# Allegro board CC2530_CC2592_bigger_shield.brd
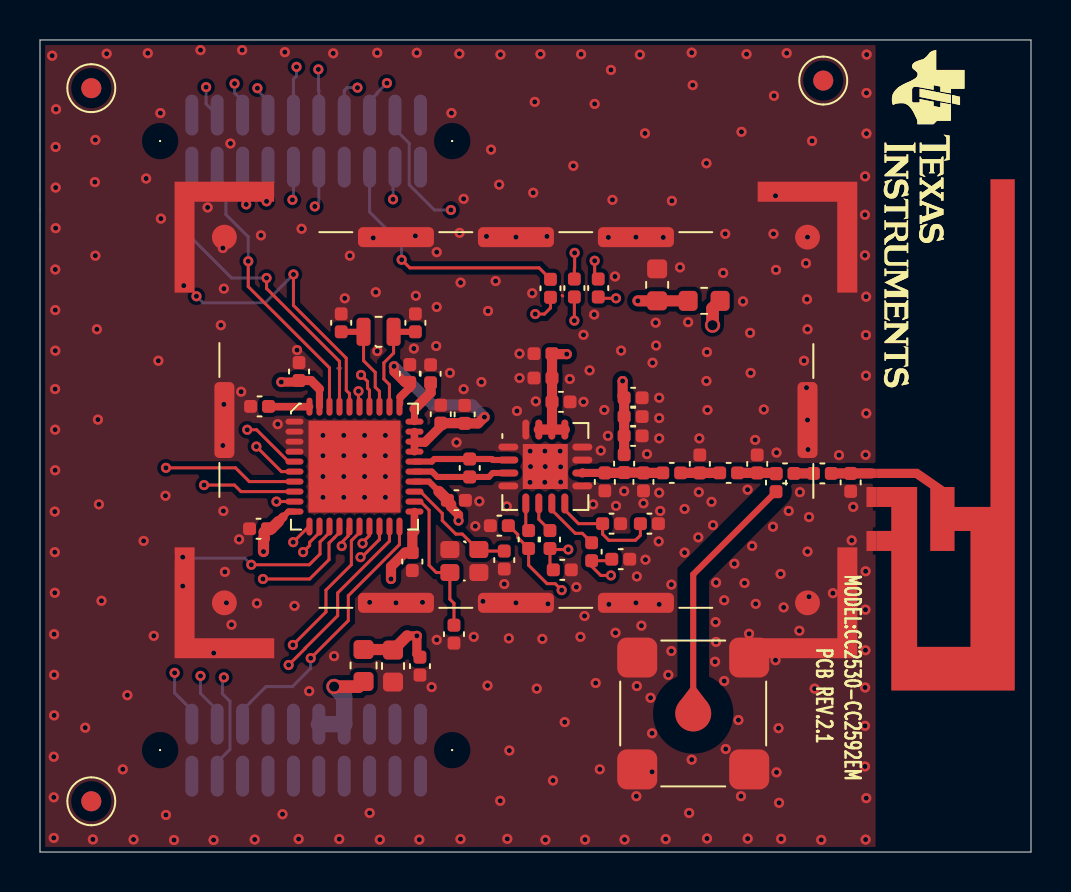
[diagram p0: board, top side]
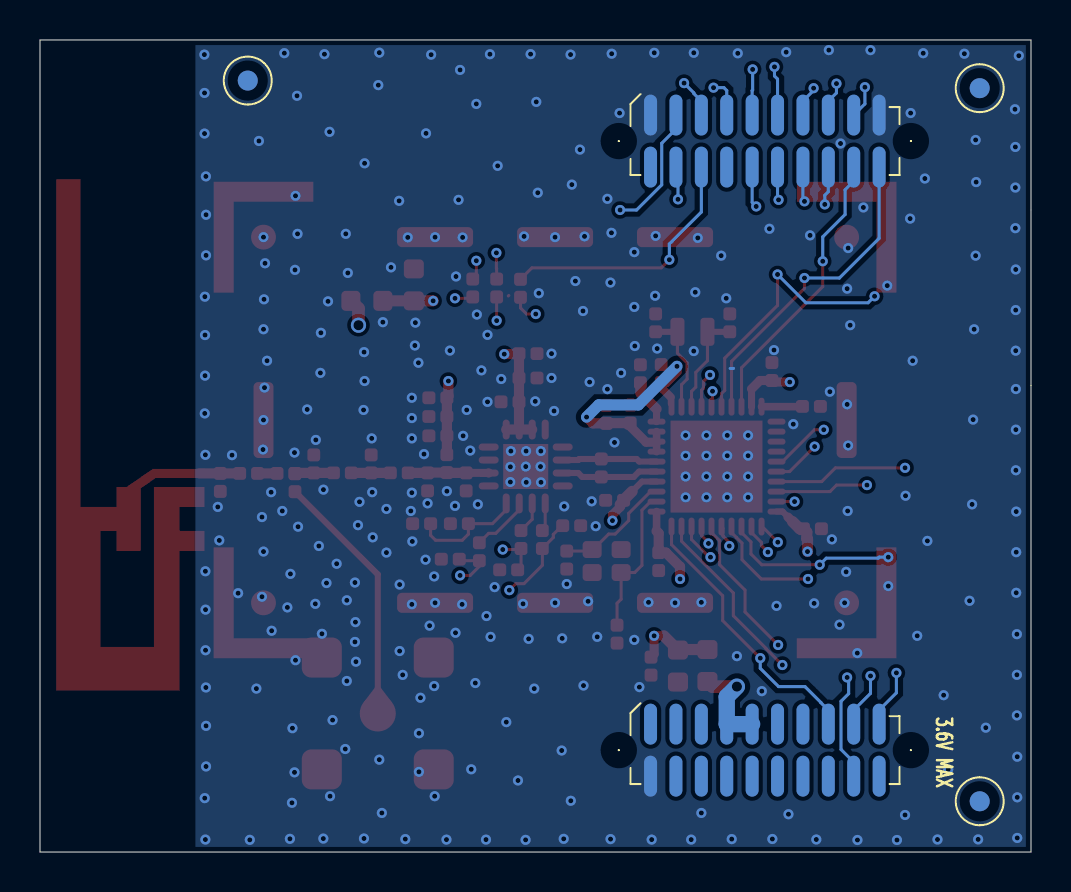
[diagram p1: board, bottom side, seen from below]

Outline 49.56 x 40.64 mm; copper layers: TOP, GND, SIGNAL_A, BOTTOM. Coordinates in mm from the lower left corner of the outline.
Outline path: 0,40.64 0,0 49.56,0 49.56,40.64 0,40.64

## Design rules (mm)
nets with their own width: min track width 0.305; nets RF_N RF_P
nets with their own width: min track width 0.457; nets VDD_CC2530
nets with their own width: min track width 0.508; nets VDD_CC2592
nets with their own width: min track width 0.635; nets VDD_EB

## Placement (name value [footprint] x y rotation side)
A2  2.4GHz  [ANTENNA_DN007AN]  41.58 18.95 270 top
C2  2.2uF  [CAPC1608X90N]  17.65 10.11 270 top
C4  DNM  [CAPC1005X60N]  19 9.75 270 top
C5  2.2uF  [CAPC1608X90N]  30.86 27.58 90 top
C101  100nF  [CAPC1005X60N]  11.38 16.18 180 top
C211  100nF  [CAPC1005X60N]  18.62 14.99 270 top
C221  12pF  [CAPC1005X60N]  20.7 11.35 270 top
C231  12pF  [CAPC1005X60N]  23.22 15.06 270 top
C241  100nF  [CAPC1005X60N]  20.37 17.6 0 top
C271  100nF  [CAPC1005X60N]  21.23 22.35 270 top
C272  220pF  [CAPC1005X60N]  20.04 21.46 90 top
C311  100nF  [CAPC1005X60N]  18.49 23.5 90 top
C321  22pF  [CAPC1005X60N]  18.77 26.04 90 top
C331  22pF  [CAPC1005X60N]  15.06 26.04 90 top
C391  1uF  [CAPC1005X60N]  12.95 23.6 90 top
C401  1uF  [CAPC1005X60N]  11.43 22.3 180 top
C3051  DNM  [CAPC1005X60N]  23.42 16.33 180 top
C3061  DNM  [CAPC1005X60N]  26.57 14.12 180 top
C3071  DNM  [CAPC1005X60N]  29.49 14.66 180 top
C3081  DNM  [CAPC1005X60N]  30.02 16.43 0 top
C3101  2.2pF  [CAPC1005X60N]  28.24 18.97 270 top
C3102  DNM  [CAPC1005X60N]  30.18 18.97 270 top
C3103  2.2pF  [CAPC1005X60N]  32.99 18.97 90 top
C3105  0.3pF  [CAPC1005X60N]  35.86 18.97 90 top
C3106  12pF  [CAPC1005X60N]  29.21 20.83 0 top
C3107  1nF  [CAPC1005X60N]  29.21 21.79 0 top
C3108  1uF  [CAPC1005X60N]  29.21 22.73 0 top
C3109  DNM  [CAPC1005X60N]  40.54 18.95 270 top
C3110  18pF  [CAPC1005X60N]  36.8 18.03 90 top
C3111  DNM  [CAPC1005X60N]  36.8 18.95 0 top
C3131  12pF  [CAPC1005X60N]  25.6 22.53 0 top
C3132  1nF  [CAPC1005X60N]  25.6 23.72 180 top
C3133  DNM  [CAPC1005X60N]  25.6 24.94 180 top
FIDU1  FIDU_1MM  [FID100X115]  2.57 2.54 180 bottom
FIDU2  FIDU_1MM  [FID100X115]  39.17 38.61 180 bottom
FIDU3  FIDU_1MM  [FID100X115]  2.57 38.23 180 bottom
FIDU4  FIDU_1MM  [FID100X115]  39.17 38.61 0 top
FIDU5  FIDU_1MM  [FID100X115]  2.57 2.54 0 top
FIDU6  FIDU_1MM  [FID100X115]  2.57 38.23 0 top
FL1  BLM18HE152SN1  [FIL_BLM18HE152SN1DN]  16.18 10.13 270 top
FL2  BLM18HE152SN1  [FIL_BLM18HE152SN1DN]  32.41 27.58 0 top
J3  SMA-10V21-TGG  [HUSTSAN_SMA10V21TGGAN]  32.66 6.93 0 top
L2526  3.9nH  [INDC1005X60N]  21.49 18.77 90 top
L3101  4.7nH  [INDC1005X60N]  29.21 19.89 270 top
L3102  1nH  [INDC1005X60N]  31.14 18.97 0 top
L3104  2nH  [INDC1005X60N]  33.99 18.97 0 top
P1  SFM-110-02-S-D-A-K-TR  [SAMTEC_SFM11002AN]  19.02 36.88 270 bottom
P2  SFM-110-02-S-D-A-K-TR  [SAMTEC_SFM11002AN]  19.02 6.4 270 bottom
R301  56k  [RESC1005X40N]  19.53 24.38 270 top
R3051  10k  [RESC1005X40N]  24.43 15.19 90 top
R3061  10k  [RESC1005X40N]  25.5 15.19 90 top
R3071  10k  [RESC1005X40N]  27.58 14.58 90 top
R3081  3.9k  [RESC1005X40N]  29.03 16.43 180 top
RP07  DNM  [RESC1005X40N]  26.72 28.68 270 top
RP10  DNM  [RESC1005X40N]  25.53 27.76 90 top
RP11  DNM  [RESC1005X40N]  27.91 28.68 270 top
RP12  0  [RESC1005X40N]  39.57 18.95 180 top
SC1  BMI-S-209-F  [MECH_BMIS209FN]  9.22 12.47 0 top
U5  CC2592  [QFNFC65P400X400X100-17AN]  23.42 20.27 270 top
U7  CC2530F256  [QFNFC50P600X600X100-41CN]  12.73 21.54 270 top
UNK#REFDES  -  []  46.23 39.14 270 top
Y1  32MHz  [XTAL_FA128N]  21.95 15.14 180 top
Y2  32.768kHz  [XTAL_FC12MN]  16.18 26.04 0 top

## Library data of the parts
A2 = ANTENNA_DN007
C2 C5 = CAPACITOR: alternate symbols: (CAPC1608X90L,CAPC1608X90M)
C4 C101 C211 C221 C231 C241 C271 C272 C311 C321 C331 C391 C401 C3051 C3061 C3071 C3081 C3101-C3103 C3105-C3111 C3131-C3133 = CAPACITOR: User Part Number: #PN; alternate symbols: (CAPC1005X60L,CAPC1005X60M)
FIDU1-FIDU6 = FIDMARK
FL1 FL2 = FILTER_2PIN: alternate symbols: (FIL_BLM18HE152SN1DL,FIL_BLM18HE152SN1DM)
J3 = CONN_COAX_1+4: alternate symbols: (HUSTSAN_SMA10V21TGGL,HUSTSAN_SMA10V21TGGM)
L2526 L3101 L3102 L3104 = INDUCTOR: alternate symbols: (INDC1005X60L,INDC1005X60M)
P1 P2 = CONN_HEADER_2X10_P_S: alternate symbols: (SAMTEC_SFM11002AL,SAMTEC_SFM11002AM)
R301 R3051 R3061 R3071 R3081 RP07 RP10-RP12 = RESISTOR: alternate symbols: (RESC1005X40L,RESC1005X40M)
SC1 = SHIELD_COVER_BMI-S-209-F: User Part Number: #PN
U5 = IC_RF_CC2592_QFN16_V1: alternate symbols: (QFNFC65P400X400X100-17AL,QFNFC65P400X400X100-17AM)
U7 = IC_RF_CC2530F256_QFN40: alternate symbols: (QFNFC50P600X600X100-41CL,QFNFC50P600X600X100-41CM,QFNFC50P600X600X100-41L,QFNFC50P600X600X100-41M)
Y1 = XTAL_4: alternate symbols: (XTAL_FA128L,XTAL_FA128M)
Y2 = XTAL: alternate symbols: (XTAL_FC12ML,XTAL_FC12MM)

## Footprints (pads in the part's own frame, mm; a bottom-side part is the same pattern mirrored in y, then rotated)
ANTENNA_DN007AN
  rect 0.46x0.5 smd: 1(0,0)
  rect 1.001x0.5 smd: 2(1.181,0) 3(3.381,0)
CAPC1005X60N
  custom 0.16x0.16 smd: 1(0,0) 2(0.899,0)
CAPC1608X90N
  custom 0.237x0.237 smd: 1(0,0) 2(1.6,0)
FID100X115
  round 1.001 smd: 1(0,0)
FIL_BLM18HE152SN1DN
  custom 0.237x0.237 smd: 1(0,0) 2(1.6,0)
HUSTSAN_SMA10V21TGGAN
  round 1.801 smd: 1(0,0)
  custom 0.5x0.5 smd: 2(-2.799,-2.799) 3(2.799,-2.799) 4(2.799,2.799) 5(-2.799,2.799)
INDC1005X60N
  custom 0.16x0.16 smd: 1(0,0) 2(0.899,0)
MECH_BMIS209FN
  custom 1.245x1.245 smd: 1(0,0) 5(29.159,0) 7(29.159,18.301) 11(0,18.301)
  custom 0.25x0.25 smd: 2(8.58,0) 3(14.58,0) 4(20.579,0) 6(29.159,9.149) 8(20.579,18.301) 9(14.58,18.301) 10(8.58,18.301) 12(0,9.149)
QFNFC50P600X600X100-41CN
  oval 0.3x0.899 smd: 1(0,0) 2(0.5,0) 3(1.001,0) 4(1.501,0) 5(1.999,0) 6(2.499,0) 7(3,0) 8(3.5,0) 9(4,0) 10(4.501,0) 21(4.501,5.999) 22(4,5.999) 23(3.5,5.999) 24(3,5.999) 25(2.499,5.999) 26(1.999,5.999) 27(1.501,5.999) 28(1.001,5.999) 29(0.5,5.999) 30(0,5.999)
  oval 0.899x0.3 smd: 11(5.25,0.749) 12(5.25,1.25) 13(5.25,1.75) 14(5.25,2.25) 15(5.25,2.751) 16(5.25,3.251) 17(5.25,3.749) 18(5.25,4.249) 19(5.25,4.75) 20(5.25,5.25) 31(-0.749,5.25) 32(-0.749,4.75) 33(-0.749,4.249) 34(-0.749,3.749) 35(-0.749,3.251) 36(-0.749,2.751) 37(-0.749,2.25) 38(-0.749,1.75) 39(-0.749,1.25) 40(-0.749,0.749)
  rect 4.6x4.6 smd: 41(2.25,3)
QFNFC65P400X400X100-17AN
  oval 0.351x1.001 smd: 1(0,0) 2(0.65,0) 3(1.3,0) 4(1.951,0) 9(1.951,3.701) 10(1.3,3.701) 11(0.65,3.701) 12(0,3.701)
  oval 1.001x0.351 smd: 5(2.824,0.874) 6(2.824,1.524) 7(2.824,2.174) 8(2.824,2.824) 13(-0.874,2.824) 14(-0.874,2.174) 15(-0.874,1.524) 16(-0.874,0.874)
  rect 2.25x2.25 smd: 17(0.975,1.849)
RESC1005X40N
  custom 0.16x0.16 smd: 1(0,0) 2(0.899,0)
SAMTEC_SFM11002AN
  round 0.099 hole 1.501 unplated: (1.3,-1.587) (1.3,13.018)
  oval 2.05x0.65 smd: 1(0,0) 2(2.603,0) 3(0,1.27) 4(2.603,1.27) 5(0,2.54) 6(2.603,2.54) 7(0,3.81) 8(2.603,3.81) 9(0,5.08) 10(2.603,5.08) 11(0,6.35) 12(2.603,6.35) 13(0,7.62) 14(2.603,7.62) 15(0,8.89) 16(2.603,8.89) 17(0,10.16) 18(2.603,10.16) 19(0,11.43) 20(2.603,11.43)
XTAL_FA128N
  custom 0.212x0.212 smd: 1(0,0) 2(1.45,0) 3(1.45,1.151) 4(0,1.151)
XTAL_FC12MN
  custom 0.175x0.175 smd: 1(0,0) 2(1.501,0)

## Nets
GND_SIGNAL: A2.2(GND_2) A2.3(GND_3) C2.2 C4.2 C5.2 C101.2 C211.2 C221.2 C231.2 C241.2 C271.1 C272.2 C311.2 C321.2 C331.2 C391.2 C401.2 C3051.2 C3061.1 C3071.1 C3081.2 C3101.2 C3102.2 C3103.2 C3105.2 C3106.2 C3107.2 C3108.2 C3109.2 C3131.2 C3132.2 C3133.2 J3.2 J3.3 J3.4 J3.5 P1.1 P1.19 P2.2 R301.1 R3081.1 SC1.1(GND#1) SC1.2(GND#2) SC1.3(GND#3) SC1.4(GND#4) SC1.5(GND#5) SC1.6(GND#6) SC1.7(GND#7) SC1.8(GND#8) SC1.9(GND#9) SC1.10(GND#10) SC1.11(GND#11) SC1.12(GND#12) U5.1(GND#1) U5.4(GND#4) U5.9(GND#9) U5.11(GND#11) U5.12(GND#12) U5.16(GND#16) U5.17(EGP/GND) U7.1(GND#1) U7.2(GND#2) U7.3(GND#3) U7.4(GND#4) U7.41(GND/EGP) Y1.2 Y1.4
VDD_CC2530: C2.1 C4.1 C101.1 C211.1 C241.1 C271.2 C272.1 C311.1 C391.1 FL1.1 U7.10(DVDD2) U7.21(AVDD5) U7.24(AVDD3) U7.27(AVDD2) U7.28(AVDD1) U7.29(AVDD4) U7.31(AVDD6) U7.39(DVDD1)
VDD_CC2592: C5.1 C3106.1 C3107.1 C3108.1 C3131.1 C3132.1 C3133.1 FL2.1 L3101.1 U5.13(VDD_LNA) U5.14(VDD_BIAS) U5.15(VDD_PA)
VDD_EB: FL1.2 FL2.2 P2.7 P2.9
ANT: C3101.1 C3102.1 L3101.2 L3102.1 U5.10(ANT)
NRESET: P2.15 U7.20(NRESET)
P0_0: P1.11 U7.19(P0_0)
P0_1: P1.5 U7.18(P0_1)
P0_2: P1.7 U7.17(P0_2)
P0_3: P1.9 U7.16(P0_3)
P0_4: P1.3 U7.15(P0_4)
P0_5: P2.18 U7.14(P0_5)
P0_6: P1.15 U7.13(P0_6)
P0_7: C3071.2 R3071.1 RP07.2 U7.12(P0_7)
P1_0: C3061.2 R3061.1 RP10.1 U7.11(P1_0)
P1_1: C3051.1 R3051.1 RP11.2 U7.9(P1_1)
P1_2: P2.17 U7.8(P1_2)
P1_3: P1.4 U7.7(P1_3)
P1_4: P1.14 U7.6(P1_4)
P1_5: P1.16 U7.5(P1_5)
P1_6: P1.18 U7.38(P1_6)
P1_7: P1.20 U7.37(P1_7)
P2_0: P2.19 U7.36(P2_0)
P2_1: P1.10 U7.35(P2_1)
P2_2: P1.12 U7.34(P2_2)
RF_N: L2526.2 U5.2(RF_N) U7.26(RF_N)
RF_P: L2526.1 U5.3(RF_P) U7.25(RF_P)
RF_SMA: C3110.1 J3.1
N16044212: C3105.1 C3110.2 C3111.1 L3104.2
N16089095: C3081.1 R3081.2 U5.8(BIAS)
N16090178: C331.1 U7.33(P2_3/XOSC32K_Q2) Y2.1
N16090485: C231.1 U7.23(XOSC_Q2) Y1.1
N16090660: C221.1 U7.22(XOSC_Q1) Y1.3
N16094002: C3103.1 L3102.2 L3104.1
N16111864: C321.1 U7.32(P2_4/XOSC32K_Q1) Y2.2
N16112528: R301.2 U7.30(RBIAS)
N16112537: C401.1 U7.40(DCOUPL)
N16121744: P1.17 RP07.1
N16121835: P1.13 RP11.1
N16121857: P1.6 RP10.2
N16154254: R3051.2 U5.5(PA_EN)
N16154263: R3061.2 U5.6(LNA_EN)
N16154275: R3071.2 U5.7(HGM)
N16168655: C3111.2 RP12.2
N16168706: A2.1(FEED_1) C3109.1 RP12.1

Pads without a net: FIDU1 1; FIDU2 1; FIDU3 1; FIDU4 1; FIDU5 1; FIDU6 1; P1 2 8; P2 1 3 4 5 6 8 10 11 12 13 14 16 20

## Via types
v1: diameter 0.508, hole 0.254, TOP to BOTTOM, 378 vias
v2: diameter 0.762, hole 0.508, TOP to BOTTOM, 2 vias

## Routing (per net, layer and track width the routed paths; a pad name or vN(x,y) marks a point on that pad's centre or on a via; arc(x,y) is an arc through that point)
GND_SIGNAL: length 0.3
  TOP w0.152: 25.5,19.19 25.57,19.19 ; 26.11,27.85 26.14,27.83
  BOTTOM w0.152: 15.04,24.2 14.89,24.2 14.88,24.21
  vias: v1(0.61,39.85) v1(0.78,35.29) v1(0.78,33.25) v1(0.78,31.22) v1(0.76,29.15) v1(0.76,27.12) v1(0.76,25.09) v1(0.76,23.17) v1(0.76,21.14) v1(0.76,19.11) v1(0.74,17.04) v1(0.74,15.01) v1(0.74,12.97) v1(0.71,10.9) v1(0.71,8.87) v1(0.71,6.84) v1(0.69,4.77) v1(0.69,2.74) v1(0.69,0.71) v1(0.8,37.17) v1(2.26,6.22) v1(2.64,0.63) v1(2.77,35.64) v1(2.74,33.53) v1(2.77,29.84) v1(2.84,26.16) v1(2.9,21.64) v1(2.95,17.4) v1(3.07,12.57) v1(3.33,39.95) v1(4.14,4.14) v1(4.37,7.85) v1(4.68,0.63) v1(5.18,15.57) v1(5.31,33.71) v1(5.39,39.98) v1(5.69,10.82) v1(5.92,24.59) v1(6.02,36.98) v1(6.05,31.7) v1(6.27,17.83) v1(6.3,1.85) v1(6.7,0.6) v1(7.14,13.31) v1(7.19,28.35) v1(8.03,40.13) v1(8.38,32.26) v1(8.68,0.6) v1(8.69,9.96) v1(9.04,26.37) v1(9.14,30.23) v1(9.14,20.35) v1(9.17,17.07) v1(9.19,28.19) v1(9.19,22.4) v1(9.25,14.02) v1(9.32,12.47) v1(9.53,35.46) v1(9.58,11.38) v1(9.96,15.65) v1(10.06,23.04) v1(10.11,40.13) v1(10.74,0.63) v1(10.85,12.45) v1(11.05,30.86) v1(11.89,21.41) v1(12.13,1.89) v1(12.24,40.03) v1(12.73,12.32) v1(12.85,25.12) v1(12.93,0.65) v1(13.08,31.19) v1(13.46,8.05) v1(14.15,20.85) v1(14.15,19.83) v1(14.15,18.79) v1(14.15,17.75) v1(14.66,39.97) v1(14.71,9.8) v1(14.97,0.65) v1(15.24,27.71) v1(15.19,20.85) v1(15.19,19.83) v1(15.19,18.79) v1(15.19,17.75) v1(15.49,29.84) v1(16.23,20.85) v1(16.23,19.83) v1(16.23,18.79) v1(16.23,17.75) v1(16.48,12.5) v1(16.48,1.96) v1(16.66,30.73) v1(16.86,40) v1(16.79,28.02) v1(16.87,25.07) v1(16.99,0.62) v1(17.27,20.85) v1(17.27,19.83) v1(17.27,18.79) v1(17.27,17.75) v1(17.8,12.47) v1(18.77,30.84) v1(18.69,25.2) v1(18.84,40) v1(18.8,27.84) v1(18.97,0.62) v1(19.13,12.5) v1(19.58,8.26) v1(19.84,30.02) v1(19.84,27.28) v1(19.81,25.32) v1(19.84,10.62) v1(20.57,36.98) v1(20.5,23.98) v1(20.83,20.5) v1(20.97,39.95) v1(20.98,30.99) v1(21.03,28.5) v1(21.03,0.65) v1(21.18,32.69) v1(21.18,23.16) v1(21.77,16.31) v1(21.69,10.77) v1(21.97,17.55) v1(22.07,23.52) v1(22.15,12.55) v1(22.33,30.81) v1(22.38,8.33) v1(22.4,27.08) v1(22.56,35.15) v1(22.78,28.57) v1(22.96,33.4) v1(23.03,39.91) v1(23.01,2.57) v1(23.22,13.41) v1(23.34,17.3) v1(23.37,0.66) v1(23.44,10.69) v1(23.47,5.08) v1(23.8,30.77) v1(23.85,22.07) v1(23.8,12.47) v1(23.98,24.94) v1(23.98,23.72) v1(24.51,20.07) v1(24.53,19.29) v1(24.5,18.5) v1(24.66,32.99) v1(24.61,27.97) v1(24.74,37.54) v1(24.79,22.56) v1(24.84,8.18) v1(25.02,39.93) v1(25.12,10.67) v1(25.25,20.07) v1(25.27,19.29) v1(25.24,18.5) v1(25.27,0.61) v1(25.35,30.81) v1(25.4,12.42) v1(25.65,3.58) v1(26.01,20.07) v1(26.04,19.28) v1(26.04,18.52) v1(26.24,6.5) v1(26.49,23.67) v1(26.67,34.34) v1(26.82,13.26) v1(27.06,39.93) v1(27.03,10.77) v1(27.18,25.88) v1(27.18,22.53) v1(27.23,11.81) v1(27.25,0.62) v1(27.48,24.1) v1(27.66,17.4) v1(27.74,37.44) v1(27.71,26.9) v1(27.79,8.46) v1(28.04,20.09) v1(27.99,4.14) v1(28.22,22.12) v1(28.42,30.76) v1(28.4,20.83) v1(28.45,12.4) v1(28.55,39.14) v1(28.63,32.64) v1(28.75,28.8) v1(28.78,10.97) v1(28.8,17.32) v1(29.06,25.1) v1(29.21,18.06) v1(29.23,0.62) v1(29.8,30.77) v1(29.84,13.79) v1(29.8,12.47) v1(29.84,8.31) v1(29.82,2.79) v1(30,39.9) v1(30.07,11.33) v1(30.18,17.45) v1(30.25,35.97) v1(30.28,14.63) v1(30.35,19.91) v1(30.53,7.72) v1(30.63,24.49) v1(30.61,5.94) v1(30.61,4.01) v1(30.78,26.49) v1(30.81,25.35) v1(30.96,22.73) v1(30.96,21.72) v1(30.96,20.7) v1(30.96,17.98) v1(30.94,15.54) v1(30.96,12.4) v1(31.01,17.07) v1(31.17,30.76) v1(31.29,0.65) v1(31.42,8.86) v1(31.57,13.39) v1(31.57,10.06) v1(31.6,32.59) v1(32,29.26) v1(32.23,17.17) v1(32.23,14.99) v1(32.41,26.52) v1(32.46,1.96) v1(32.59,40) v1(32.64,38.38) v1(32.59,4.62) v1(32.97,20.7) v1(32.94,18.01) v1(32.92,15.75) v1(33.32,34.47) v1(33.35,25.02) v1(33.32,23.57) v1(33.38,22.12) v1(33.36,0.68) v1(33.58,17.53) v1(33.65,16.36) v1(33.78,11.51) v1(33.76,9.53) v1(33.81,13.49) v1(33.81,10.52) v1(34.16,28.98) v1(34.26,30.94) v1(34.21,12.6) v1(34.21,8.56) v1(34.29,5.16) v1(34.72,14.43) v1(34.92,6.6) v1(35.08,36.04) v1(35.05,2.79) v1(35.15,27.56) v1(35.23,13.46) v1(35.33,39.93) v1(35.38,18.14) v1(35.46,10.92) v1(35.39,0.67) v1(35.51,25.98) v1(35.53,23.98) v1(35.61,15.32) v1(35.76,20.62) v1(35.79,12.42) v1(36.2,22.15) v1(36.68,30.94) v1(36.65,16.28) v1(36.7,37.85) v1(36.78,32.84) v1(36.78,9.6) v1(36.8,29.13) v1(36.83,19.99) v1(36.83,3.99) v1(36.93,6.2) v1(36.96,2.46) v1(37.03,13.92) v1(37.06,0.66) v1(37.19,12.24) v1(37.34,39.98) v1(37.44,17.07) v1(37.97,11.07) v1(38,18.01) v1(38.2,24.59) v1(38.38,30.77) v1(38.3,29.46) v1(38.35,27.66) v1(38.38,26.16) v1(38.33,23.24) v1(38.38,21.62) v1(38.38,15.04) v1(38.4,20.14) v1(38.46,16.76) v1(38.46,12.78) v1(38.61,35.59) v1(38.73,8.18) v1(39.07,0.61) v1(39.65,12.95) v1(39.95,19.86) v1(40.67,17.27) v1(40.59,15.6) v1(41.26,33.81) v1(41.25,31.89) v1(41.25,29.86) v1(41.28,12.13) v1(41.28,10.1) v1(41.26,8.23) v1(41.25,6.31) v1(41.25,4.28) v1(41.34,39.91) v1(41.33,37.99) v1(41.33,35.96) v1(41.31,27.79) v1(41.3,25.87) v1(41.3,23.84) v1(41.32,21.95) v1(41.29,19.88) v1(41.29,14.05) v1(41.32,2.7) v1(41.29,0.62)
VDD_CC2530: length 66.7
  TOP w0.203: U7.31 17.98,22.4 18.01,22.43
  TOP w0.305: 21.23,21.46 C271.2 ; 19.95,18.05 19.45,18.54 U7.24 ; 12.15,16.77 12.43,17.04 U7.10 ; 18.01,22.76 18.01,22.43
  TOP w0.356: U7.39 13.98,23.17
  TOP w0.381: U7.29 U7.28 U7.27 ; U7.21 18.72,16.06
  TOP w0.406: 18.49,23.24 18.01,22.76
  TOP w0.457: v1(20.93,16.59) 20.93,16.88 20.54,17.27 20.54,17.39 ; 18.49,23.24 C311.1 18.24,23.5 17.7,24.03 v1(17.7,24.31) ; 17.63,10.13 C2.1 ; C272.1 20.04,21.3 19.25,20.51 18.72,20.51 ; C4.1 18.85,9.91 v1(18.85,10.82) 18.36,10.82 ; v1(12.07,23.52) 12.88,23.52 C391.1 13.55,23.6 13.98,23.17 ; 11.92,16.54 12.15,16.77
  TOP w0.508: v1(17.55,13.67) 17.55,14.28 18.25,14.99 C211.1 18.62,15.95 18.72,16.06 ; C271.2 21.91,21.45 v1(22.23,21.77) ; C272.1 21.23,21.46
  TOP w0.559: C2.1 18.36,10.82 ; FL1.1 17.63,10.13 ; 19.95,18.05 20.37,17.62 C241.1 20.37,17.56 20.54,17.39 ; 11.92,16.54 11.57,16.18 C101.1 11.21,16.01 11.21,15.69 11.18,15.65 v1(11.18,15.04)
  SIGNAL_A w0.559: v1(18.85,10.82) 15.39,10.82 v1(11.18,15.04) 11.18,15.7 11,15.88 11,18.41 12.8,20.22 12.8,22.78 ; 12.8,22.78 v1(12.07,23.52) ; 12.8,22.78 13.18,22.4 16.41,22.4 17.7,23.7 v1(17.7,24.31) ; v1(17.55,13.67) 18.62,13.67 20.93,15.98 v1(20.93,16.59) 20.93,18.49 21.76,19.32 21.76,21.3 v1(22.23,21.77)
  BOTTOM w0.559: v1(22.23,21.77) 21.62,22.38 19.63,22.38 v1(17.7,24.31)
VDD_CC2592: length 19
  TOP w0.508: L3101.1 C3106.1 C3107.1 C3108.1 29.13,22.81 v1(29.13,23.57) ; U5.14 25.6,21.15 C3131.1 C3132.1 C3133.1 25.63,24.92 v1(26.34,24.92) ; U5.14 U5.15 ; U5.14 U5.13
  TOP w0.559: v1(29.9,27.58) C5.1 FL2.1
  SIGNAL_A w0.559: 27.79,24.92 27.79,25.2 29.9,27.3 v1(29.9,27.58) ; 27.79,24.92 v1(29.13,23.57) ; 27.79,24.92 v1(26.34,24.92)
VDD_EB: length 41.2
  TOP w0.635: FL1.2 15.93,8.28 v2(14.71,8.28) ; v2(33.63,26.37) 33.63,27.2 FL2.2
  SIGNAL_A w0.762: v2(14.71,8.28) 15.21,8.79 15.23,8.79 15.94,9.5 29.85,9.5 32.66,12.31 32.66,13.89 34.54,15.77 34.54,25.45 v2(33.63,26.37)
  BOTTOM w0.813: v2(14.71,8.28) 15.21,7.77 P2.7 P2.9
ANT: length 4
  TOP w0.406: C3101.1 27.12,18.97
  TOP w0.457: 27.12,18.97 U5.10
  TOP w0.508: 30.16,18.99 L3101.2 29.19,18.97 C3101.1 ; C3102.1 L3102.1
  TOP w0.559: C3102.1 30.16,18.99
NRESET: length 13.9
  TOP w0.152: v1(13.54,9.7) 15.42,11.58 15.42,12.83 17.98,15.38 U7.20
  BOTTOM w0.152: P2.15 10.13,7.1 10.51,7.48 10.51,7.49 11.3,8.28 12.62,8.28 13.54,9.19 v1(13.54,9.7)
P0_0: length 58.9
  TOP w0.152: v1(12.43,9.36) 13.26,10.19 13.26,10.2 14.88,11.83 14.88,12.97 17.48,15.56 U7.19
  SIGNAL_A w0.152: v1(12.83,39.29) 11.86,39.29 11.66,39.5 6.96,39.5 3.96,36.5 3.96,9.53 6.17,7.32 10.39,7.32 v1(12.43,9.36)
  BOTTOM w0.152: v1(12.83,39.29) 12.83,38.84 12.67,38.68 P1.11
P0_1: length 31.7
  TOP w0.152: U7.18 16.97,15.64 16.09,14.76 v1(16.03,14.76)
  SIGNAL_A w0.152: v1(17.35,38.48) 17.35,35.74 20.09,33 20.09,31.94 20.37,31.66 20.37,24.59 19.89,24.11 19.89,16.94 17.7,14.76 v1(16.03,14.76)
  BOTTOM w0.152: P1.5 16.48,37.58 16.86,37.96 16.86,37.99 v1(17.35,38.48)
P0_2: length 29.4
  TOP w0.152: v1(16.13,15.44) 16.13,15.49 16.47,15.84 U7.17
  SIGNAL_A w0.152: v1(15.88,38.25) 15.88,35.97 19.33,32.51 19.33,17.09 17.68,15.44 v1(16.13,15.44)
  BOTTOM w0.152: v1(15.88,38.25) 15.36,38.25 15.21,38.11 P1.7
P0_3: length 57
  TOP w0.152: v1(12.65,10.36) 14.3,12.02 14.3,13.11 15.57,14.38 15.57,15.58 15.98,15.99 U7.16
  SIGNAL_A w0.152: v1(13.92,39.17) 13.44,38.68 11.33,38.68 10.9,39.12 7.34,39.12 4.47,36.25 4.47,9.93 6.5,7.9 10.18,7.9 v1(12.65,10.36)
  BOTTOM w0.152: v1(13.92,39.17) 13.92,38.14 13.94,38.11 P1.9
P0_4: length 30.9
  TOP w0.152: v1(15.09,15.31) 15.09,15.5 15.39,15.8 15.39,15.82 15.41,15.83 15.41,16.2 15.48,16.24 U7.15
  SIGNAL_A w0.152: v1(20.55,32.13) 20.87,31.81 20.95,31.81 21.49,31.27 21.49,24.23 20.37,23.11 20.37,16.64 17.98,14.25 15.69,14.25 15.09,14.86 v1(15.09,15.31)
  BOTTOM w0.152: P1.3 17.75,36.18 18.47,35.47 18.47,33.39 19.72,32.13 v1(20.55,32.13)
P0_5: length 17
  TOP w0.152: U7.14 14.98,15.99 14.72,15.74 14.72,15.74 14.45,15.46 14.45,14.63 13.48,13.67 v1(11.15,13.67)
  SIGNAL_A w0.152: v1(9.19,8.74) 9.19,9.39 9.37,9.56 9.37,9.58 11.48,11.68 11.48,13.34 v1(11.15,13.67)
  BOTTOM w0.152: v1(9.19,8.74) 9.12,8.66 9.12,7.92 9.5,7.54 9.5,5.13 8.86,4.5 P2.18
P0_6: length 38.4
  TOP w0.152: v1(10.57,14.38) 13.46,14.38 14,14.91 14,15.52 14.48,15.99 U7.13
  SIGNAL_A w0.152: v1(7.14,14.76) 5.21,16.69 5.21,32.21 7.39,34.39 7.39,38.15 8.05,38.81 9.37,38.81 v1(9.73,38.46)
  BOTTOM w0.152: P1.15 10.13,37.58 9.73,37.99 v1(9.73,38.46) ; v1(7.14,14.76) 7.59,14.76 7.65,14.71 10.24,14.71 v1(10.57,14.38)
P0_7: length 42.8
  TOP w0.152: v1(13.16,15.01) 13.48,15.34 13.48,15.5 13.98,15.99 U7.12 ; v1(26.72,26.59) RP07.2 ; v1(28.55,13.84) 28.04,13.84 27.58,14.3 R3071.1 28.51,14.58 C3071.2
  SIGNAL_A w0.152: v1(26.72,26.59) 26.26,26.14 23.9,26.14 23.24,25.48 23.24,20.93 22.89,20.58 22.89,16.25 23.47,15.67 26.72,15.67 v1(28.55,13.84) 24.36,13.84 24.15,14.05 22.23,14.05 20.17,11.99 16.18,11.99 v1(13.16,15.01)
P1_0: length 37.1
  TOP w0.152: v1(12.66,15.51) 13.44,16.29 U7.11 ; C3061.2 25.67,14.17 25.5,14.34 R3061.1 25.55,15.14 v1(26.42,15.14) ; RP10.1 25.53,27.23 25.22,26.92 v1(24.77,26.92)
  SIGNAL_A w0.152: v1(12.66,15.51) 13.58,15.51 15.93,13.16 19.66,13.16 21.03,14.53 25.81,14.53 v1(26.42,15.14) 23.01,15.14 22.48,15.67 22.48,20.93 22.76,21.21 22.76,25.91 23.77,26.92 v1(24.77,26.92)
P1_1: length 49
  TOP w0.152: U7.9 v1(11.82,17.54) ; RP11.2 27.98,27.71 v1(28.8,27.71) ; v1(26.09,13.11) 25.76,13.43 25.35,13.43 24.43,14.35 R3051.1 24.43,15.19 23.89,15.74 23.89,15.89 23.45,16.33 C3051.1
  SIGNAL_A w0.152: v1(28.8,27.71) 29.57,28.47 31.24,28.47 31.62,28.09 31.62,14.5 30.25,13.13 28.02,13.13 27.64,12.75 26.44,12.75 v1(26.09,13.11) 26.09,12.04 25.58,11.53 15.67,11.53 11.82,15.38 v1(11.82,17.54)
P1_2: length 17.3
  TOP w0.152: U7.8 10.05,18.04 9.73,18.36 v1(8.2,18.36)
  SIGNAL_A w0.152: v1(8.03,8.81) 8.03,10.39 8.56,10.92 8.56,17.17 8.2,17.53 v1(8.2,18.36)
  BOTTOM w0.152: P2.17 8.86,7.1 8.03,7.94 v1(8.03,8.81)
P1_3: length 33.1
  TOP w0.152: U7.7 10.46,18.54 9.78,19.23 v1(6.3,19.23)
  SIGNAL_A w0.152: v1(6.3,19.23) 6.3,22.45 6.5,22.66 6.5,31.29 8.89,33.68 16.64,33.68 v1(17.65,32.66)
  BOTTOM w0.152: P1.4 17.65,34.18 v1(17.65,32.66)
P1_4: length 17.1
  TOP w0.152: v1(10.82,20.29) 12.07,19.04 U7.6
  SIGNAL_A w0.152: v1(10.82,20.29) 11.28,20.75 11.28,25.14 11.81,25.68 11.81,32.08 v1(11.33,32.56)
  BOTTOM w0.152: P1.14 11.4,32.64 v1(11.33,32.56)
P1_5: length 16.9
  TOP w0.152: U7.5 12.42,19.54 10.83,21.13 v1(10.36,21.13)
  SIGNAL_A w0.152: v1(10.31,32.41) 10.31,30.55 9.86,30.1 9.86,28.18 10.69,27.35 10.69,21.46 v1(10.36,21.13)
  BOTTOM w0.152: v1(10.31,32.41) 10.31,32.87 10.13,33.05 P1.16
P1_6: length 14.3
  TOP w0.152: U7.38 14.48,24.23 10.41,28.3 v1(10.41,29.57)
  BOTTOM w0.152: P1.18 8.86,33.58 9.3,33.14 9.3,31.9 10.41,30.79 v1(10.41,29.57)
P1_7: length 16.1
  TOP w0.152: v1(11.33,28.73) 11.33,28.2 14.98,24.56 U7.37
  BOTTOM w0.152: P1.20 7.59,30.71 9.58,28.73 v1(11.33,28.73)
P2_0: length 36.1
  TOP w0.152: U7.36 15.48,22.94 15.32,23.1 15.32,24.71 12.67,27.36 v1(12.67,28.91)
  SIGNAL_A w0.152: v1(6.73,8.97) 6.73,11.58 8,12.85 8,16 7.32,16.69 7.32,27.3 v1(7.82,27.81)
  BOTTOM w0.152: v1(12.67,28.91) 11.26,27.49 8.15,27.49 v1(7.82,27.81) ; P2.19 7.59,7.1 6.73,7.97 v1(6.73,8.97)
P2_1: length 13.3
  TOP w0.152: v1(15.93,23.06) 15.93,22.34 U7.35
  SIGNAL_A w0.152: v1(13.74,32.31) 13.74,24.79 15.47,23.06 v1(15.93,23.06)
  BOTTOM w0.152: P1.10 13.94,32.51 v1(13.74,32.31)
P2_2: length 14.8
  TOP w0.152: U7.34 16.47,23.11 16.38,23.21 16.38,23.25 16.38,23.26 16.38,23.55 v1(16.05,23.88)
  SIGNAL_A w0.152: v1(16.05,23.88) 14.58,25.35 14.58,32.33 13.95,32.96 12.95,32.96 v1(12.62,32.64)
  BOTTOM w0.152: P1.12 12.67,32.69 v1(12.62,32.64)
RF_N: length 4.8
  TOP w0.305: U7.26 19.59,19.54 19.72,19.67 L2526.2 22.59,19.67 22.64,19.62 U5.2
RF_P: length 4.9
  TOP w0.305: U5.3 22.64,18.97 22.44,18.77 L2526.1 19.87,18.77 19.6,19.04 U7.25
RF_SMA: length 12.8
  TOP w0.152: 36.8,18.05 C3110.1
  TOP w0.305: J3.1 32.66,13.89 C3110.1
N16044212: length 2
  TOP w0.152: 36.76,18.97 36.78,18.97 C3111.1
  TOP w0.508: L3104.2 C3105.1 36.76,18.97
  TOP w0.559: 36.76,18.97 C3110.2
N16089095: length 5.7
  TOP w0.152: U5.8 26.24,17.12 26.93,16.43 R3081.2 28.13,15.91 28.44,15.6 29.78,15.6 30.02,15.85 C3081.1
N16090178: length 5.2
  TOP w0.152: Y2.1 16.18,24.59 16.76,24 16.76,23.27 16.97,23.06 U7.33
  TOP w0.305: Y2.1 C331.1
N16090485: length 5.9
  TOP w0.152: C231.1 22.02,15.06 Y1.1 21.89,15.14 21.12,15.91 20.79,15.91 20.12,16.59 20.12,16.95 19.02,18.04 U7.23
N16090660: length 7.6
  TOP w0.152: U7.22 19.02,17.54 19.46,17.11 19.46,14.35 19.82,13.99 Y1.3 20.5,12.65 20.7,12.45 C221.1
N16094002: length 1.9
  TOP w0.508: L3102.2 C3103.1 L3104.1
N16111864: length 5.2
  TOP w0.152: U7.32 17.48,23.39 17.2,23.67 17.2,24.48 17.68,24.97 Y2.2
  TOP w0.305: C321.1 Y2.2
N16112528: length 2.3
  TOP w0.356: 18.72,22.17 U7.30
  TOP w0.508: R301.2 19.53,22.98 18.72,22.17
N16112537: length 2
  TOP w0.381: U7.40 11.44,22.29
  TOP w0.457: 11.44,22.29 C401.1
N16121744: length 27.6
  TOP w0.152: RP07.1 26.72,29.2 26.73,29.22 v1(26.73,29.98)
  SIGNAL_A w0.152: v1(8.31,38.28) 9.42,37.16 13.64,37.16 15.42,38.94 19.96,38.94 26.39,32.51 26.39,30.33 v1(26.73,29.98)
  BOTTOM w0.152: P1.17 8.31,37.44 v1(8.31,38.28)
N16121835: length 25.6
  TOP w0.152: v1(27.74,29.59) 27.74,28.85 RP11.1
  SIGNAL_A w0.152: v1(27.74,29.59) 27.74,32.16 20.47,39.42 15.06,39.42 13.72,38.07 11.48,38.07 11.33,38.23 v1(10.87,38.23)
  BOTTOM w0.152: P1.13 11.4,37.58 10.87,38.12 v1(10.87,38.23)
N16121857: length 13.1
  TOP w0.152: RP10.2 25.53,28.67 24.96,29.24 18.49,29.24 v1(18.08,29.64)
  BOTTOM w0.152: v1(18.08,29.64) 18.08,30.43 16.48,32.03 P1.6
N16154254: length 1.4
  TOP w0.152: U5.5 24.29,16.23 R3051.2
N16154263: length 1.6
  TOP w0.152: U5.6 24.94,16.65 25.5,16.09 R3061.2
N16154275: length 3
  TOP w0.152: U5.7 25.59,17.12 26.76,15.95 27.12,15.95 27.58,15.48 R3071.2
N16168655: length 1
  TOP w0.508: C3111.2 RP12.2
N16168706: length 2
  TOP w0.508: RP12.1 C3109.1 A2.1

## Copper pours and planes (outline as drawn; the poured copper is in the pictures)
GND_SIGNAL on TOP: 0.26,0.26 0.26,40.38 41.78,40.38 41.78,0.26 ; 4 cut-outs
GND_SIGNAL on BOTTOM, GND: 0.26,0.26 0.26,40.38 41.78,40.38 41.78,0.26
GND_SIGNAL on SIGNAL_A: 0.26,0.26 0.26,40.38 41.78,40.38 41.78,0.26 ; 2 cut-outs
Net_2 on TOP (solid shape): 48.74,8.09 42.57,8.09 42.57,15.07 41.83,15.07 41.83,16.07 42.57,16.07 42.57,17.27 41.83,17.27 41.83,18.27 43.86,18.27 43.86,10.27 46.53,10.27 46.53,16.07 45.73,16.07 45.73,15.07 44.52,15.07 44.52,18.2 43.76,18.72 41.83,18.72 41.83,19.18 43.91,19.18 45.23,18.27 45.73,18.27 45.73,17.27 47.53,17.27 47.53,33.67 48.74,33.67

Small or netless copper shapes (teardrops, artwork), in the pictures only: 1 on TOP

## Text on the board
Ref Des/Silkscreen Bottom: 3.6V MAX
Ref Des/Silkscreen Top: PCB REV.2.1 | MODEL:CC2530-CC2592EM
XSECTION_CHART: *  SURFACE - AIR 0 MIL | L1: TOP CONDUCTOR - COPPER 1.4 MIL | *  DIELECTRIC - FR-4 6.8 MIL | L2: GND PLANE - COPPER 0.7 MIL | *  DIELECTRIC - FR-4 44.8 MIL | L3: SIGNAL_A PLANE - COPPER 0.7 MIL | L4: BOTTOM CONDUCTOR - COPPER 1.4 MIL | DESIGN CROSS SECTION CHART | ___________________________ | TOTAL THICKNESS 62.9 MIL
BODY_CENTER: FIGURE | SIZE | 10.0 | 20.0 | 59.1 | DRILL CHART: TOP to BOTTOM | ALL UNITS ARE IN MILS | TOLERANCE | +3.0/-3.0 | +0.0/-0.0 | PLATED | NON-PLATED | QTY | 378 | 2 | 4
